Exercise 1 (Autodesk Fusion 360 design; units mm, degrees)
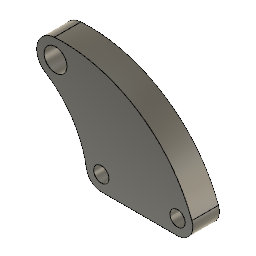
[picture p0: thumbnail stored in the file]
sketch "Sketch1" plane through (0, 0, 0) normal (0, 1, 0) x axis (1, 0, 0)
  line L1 (100, 20) -> (0, 20)
  arc A1 centre (-138.2488, 22.0743) radius 120 clockwise from (-19.7498, 3.1535) to (-73.4912, -78.9527)
  arc A2 centre (-50.3593, 54.6999) radius 180 clockwise from (118.7949, -6.8375) to (-61.555, -124.9516)
  arc A3 centre (-60, -100) radius 25 clockwise from (-61.555, -124.9516) to (-73.4912, -78.9527)
  arc A4 centre (0, 0) radius 20 clockwise from (-19.7498, 3.1535) to (0, 20)
  arc A5 centre (100, 0) radius 20 clockwise from (100, 20) to (118.7949, -6.8375)
  circle C1 centre (-60, -100) radius 15
  circle C2 centre (0, 0) radius 10
  circle C3 centre (100, 0) radius 10
  point P1 (0, 0)
  point P2 (0, 0)
  point P4 (100, 0)
  point P3 (-60, -100)
  coincident P1 P2
  equal A4 A5
  horizontal P2 P4
  tangent L1 A5
  tangent A2 A3
  tangent A2 A5
  tangent A1 A3
  tangent A1 A4
  tangent L1 A4
  concentric A3 C1
  concentric A4 C2
  concentric A5 C3
  equal C2 C3
  dimension "d1" radius A4 = 20
  dimension "d2" distance P2 P3 = 100
  dimension "d3" distance P2 P4 = 100
  dimension "d4" distance P2 P3 = 60
  dimension "d5" radius A3 = 25
  dimension "d6" radius A2 = 180
  dimension "d7" radius A1 = 120
  dimension "d8" diameter C1 = 30
  dimension "d9" diameter C2 = 20
extrude "Extrude1" new body sketch "Sketch1" along normal blind 35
